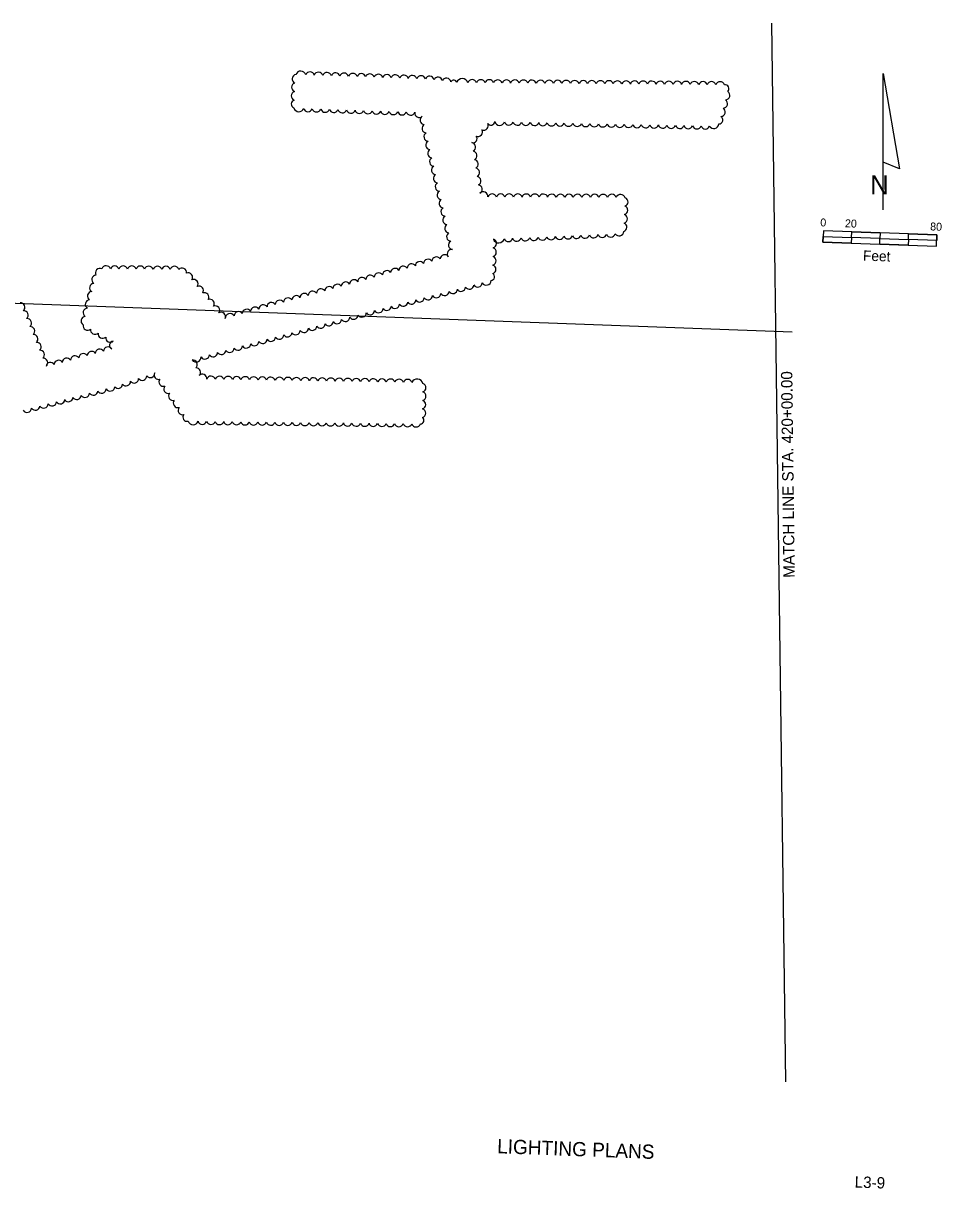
# Model space of a CAD drawing. Extents: x 919231 to 920524, y 636539 to 637379.
# Drawn here: x 919878 to 920524, y 636539 to 637359 of the extents above; entities that cross this region are included whole.
import ezdxf

# ---------------------------------------------------------------- set-up
doc = ezdxf.new("R2010")
doc.units = 0
for name, color, linetype in [('ActivePointCell_dp', 7, 'Continuous'), ('Cloud_dp', 7, 'Continuous'), ('MatchLines_dp', 7, 'Continuous'), ('NorthArw_dp', 7, 'Continuous'), ('Scale_dp', 7, 'Continuous'), ('TextMisc', 7, 'Continuous'), ('TextShtNo', 7, 'Continuous')]:
    doc.layers.add(name, color=color, linetype=linetype)

msp = doc.modelspace()

# ---------------------------------------------------------------- linework, layer by layer
at = {"layer": 'ActivePointCell_dp'}
msp.add_line((919374.23, 637180.22), (920419.17, 637141.7), dxfattribs=at)
at = {"layer": 'Cloud_dp'}
for centre, radius, start, end in [((920070.6, 637319.6), 3.18, 100.2465, 245.2465), ((920073.46, 637321.53), 3.63, 15.52249, 160.52249), ((920079.92, 637321.44), 3.15, 15.52249, 160.52249), ((920085.93, 637321.24), 3.15, 15.52249, 160.52249), ((920091.95, 637321.03), 3.15, 15.52249, 160.52249), ((920097.96, 637320.82), 3.15, 15.52249, 160.52249), ((920103.97, 637320.61), 3.15, 15.52249, 160.52249), ((920109.98, 637320.41), 3.15, 15.52249, 160.52249), ((920115.99, 637320.2), 3.15, 15.52249, 160.52249), ((920122, 637319.99), 3.15, 15.52249, 160.52249), ((920128.02, 637319.78), 3.15, 15.52249, 160.52249), ((920134.03, 637319.58), 3.15, 15.52249, 160.52249), ((920140.04, 637319.37), 3.15, 15.52249, 160.52249), ((920146.05, 637319.16), 3.15, 15.52249, 160.52249), ((920152.06, 637318.95), 3.15, 15.52249, 160.52249), ((920158.07, 637318.75), 3.15, 15.52249, 160.52249), ((920070.12, 637313.68), 3.15, 105.52249, 250.52249), ((920164.08, 637318.35), 3.22, 12.29046, 157.29046), ((920170.03, 637317.74), 3.09, 10.36222, 155.36222), ((920175.94, 637316.99), 3.15, 10.36222, 155.36222), ((920181.04, 637316.64), 2.19, 10.36222, 155.36222), ((920187.11, 637315.76), 4.12, 16.96357, 161.96357), ((920194.05, 637315.99), 3.15, 17.02441, 162.02441), ((920200.06, 637315.94), 3.15, 17.02441, 162.02441), ((920206.08, 637315.89), 3.15, 17.02441, 162.02441), ((920212.09, 637315.84), 3.15, 17.02441, 162.02441), ((920218.11, 637315.79), 3.15, 17.02441, 162.02441), ((920224.12, 637315.74), 3.15, 17.02441, 162.02441), ((920230.14, 637315.69), 3.15, 17.02441, 162.02441), ((920236.15, 637315.64), 3.15, 17.02441, 162.02441), ((920242.17, 637315.59), 3.15, 17.02441, 162.02441), ((920248.18, 637315.54), 3.15, 17.02441, 162.02441), ((920254.2, 637315.49), 3.15, 17.02441, 162.02441), ((920260.21, 637315.44), 3.15, 17.02441, 162.02441), ((920266.23, 637315.39), 3.15, 17.02441, 162.02441), ((920272.24, 637315.34), 3.15, 17.02441, 162.02441), ((920278.26, 637315.29), 3.15, 17.02441, 162.02441), ((920284.27, 637315.24), 3.15, 17.02441, 162.02441), ((920290.29, 637315.19), 3.15, 17.02441, 162.02441), ((920296.3, 637315.14), 3.15, 17.02441, 162.02441), ((920302.32, 637315.09), 3.15, 17.02441, 162.02441), ((920308.33, 637315.04), 3.15, 17.02441, 162.02441), ((920314.35, 637314.99), 3.15, 17.02441, 162.02441), ((920320.36, 637314.94), 3.15, 17.02441, 162.02441), ((920326.38, 637314.89), 3.15, 17.02441, 162.02441), ((920332.39, 637314.84), 3.15, 17.02441, 162.02441), ((920338.41, 637314.79), 3.15, 17.02441, 162.02441), ((920344.42, 637314.74), 3.15, 17.02441, 162.02441), ((920350.44, 637314.69), 3.15, 17.02441, 162.02441), ((920356.45, 637314.64), 3.15, 17.02441, 162.02441), ((920362.47, 637314.59), 3.15, 17.02441, 162.02441), ((920368.48, 637314.54), 3.15, 17.02441, 162.02441), ((920371.96, 637312.68), 2.81, 314.36029, 99.36029), ((920069.91, 637307.66), 3.15, 105.52249, 250.52249), ((920372.21, 637308.03), 3.15, 271.96447, 56.96447), ((920069.62, 637301.96), 2.84, 105.52249, 250.52249), ((920072.18, 637300.16), 3.62, 193.99327, 338.99327), ((920078.6, 637299.7), 3.15, 195.52249, 340.52249), ((920084.61, 637299.5), 3.15, 195.52249, 340.52249), ((920090.63, 637299.29), 3.15, 195.52249, 340.52249), ((920096.64, 637299.08), 3.15, 195.52249, 340.52249), ((920102.65, 637298.87), 3.15, 195.52249, 340.52249), ((920108.66, 637298.67), 3.15, 195.52249, 340.52249), ((920114.67, 637298.46), 3.15, 195.52249, 340.52249), ((920120.69, 637298.25), 3.15, 195.52249, 340.52249), ((920126.7, 637298.04), 3.15, 195.52249, 340.52249), ((920368.98, 637296.44), 3.15, 271.96447, 56.96447), ((920370.59, 637302.23), 3.15, 271.96447, 56.96447), ((920132.71, 637297.84), 3.15, 195.52249, 340.52249), ((920138.72, 637297.63), 3.15, 195.52249, 340.52249), ((920144.73, 637297.42), 3.15, 195.52249, 340.52249), ((920150.74, 637297.21), 3.15, 195.52249, 340.52249), ((920156.78, 637295.6), 3.12, 169.68331, 314.68331), ((920160.56, 637290.67), 3.15, 120.30502, 265.30502), ((920207.23, 637289.73), 2.65, 211.4846, 356.4846), ((920213.36, 637290.58), 3.62, 196.3247, 341.3247), ((920219.82, 637290.31), 3.15, 196.3247, 341.3247), ((920225.83, 637290.18), 3.15, 196.3247, 341.3247), ((920231.84, 637290.06), 3.15, 196.3247, 341.3247), ((920237.86, 637289.94), 3.15, 196.3247, 341.3247), ((920243.87, 637289.81), 3.15, 196.3247, 341.3247), ((920367.5, 637290.83), 2.92, 271.96447, 56.96447), ((920161.9, 637284.8), 3.15, 120.30502, 265.30502), ((920163.23, 637278.93), 3.15, 120.30502, 265.30502), ((920198.19, 637282.31), 3.15, 245.167, 30.167), ((920202.24, 637286.76), 3.15, 245.167, 30.167), ((920249.89, 637289.69), 3.15, 196.3247, 341.3247), ((920255.9, 637289.57), 3.15, 196.3247, 341.3247), ((920261.91, 637289.44), 3.15, 196.3247, 341.3247), ((920267.93, 637289.32), 3.15, 196.3247, 341.3247), ((920273.94, 637289.2), 3.15, 196.3247, 341.3247), ((920279.96, 637289.07), 3.15, 196.3247, 341.3247), ((920285.97, 637288.95), 3.15, 196.3247, 341.3247), ((920291.98, 637288.83), 3.15, 196.3247, 341.3247), ((920298, 637288.7), 3.15, 196.3247, 341.3247), ((920304.01, 637288.58), 3.15, 196.3247, 341.3247), ((920310.03, 637288.46), 3.15, 196.3247, 341.3247), ((920316.04, 637288.33), 3.15, 196.3247, 341.3247), ((920322.05, 637288.21), 3.15, 196.3247, 341.3247), ((920328.07, 637288.09), 3.15, 196.3247, 341.3247), ((920334.08, 637287.96), 3.15, 196.3247, 341.3247), ((920340.1, 637287.84), 3.15, 196.3247, 341.3247), ((920346.11, 637287.72), 3.15, 196.3247, 341.3247), ((920352.12, 637287.59), 3.15, 196.3247, 341.3247), ((920358.14, 637287.47), 3.15, 196.3247, 341.3247), ((920364.13, 637288.21), 3.48, 210.14773, 355.14773), ((920164.56, 637273.07), 3.15, 120.30502, 265.30502), ((920194.57, 637277.6), 2.94, 253.86781, 38.86781), ((920193.28, 637271.61), 3.2, 296.5074, 81.5074), ((920165.9, 637267.2), 3.15, 120.30502, 265.30502), ((920194.25, 637265.63), 3.15, 296.5074, 81.5074), ((920167.23, 637261.34), 3.15, 120.30502, 265.30502), ((920168.56, 637255.47), 3.15, 120.30502, 265.30502), ((920195.19, 637259.69), 3.15, 296.5074, 81.5074), ((920196.13, 637253.75), 3.15, 296.5074, 81.5074), ((920169.9, 637249.61), 3.15, 120.30502, 265.30502), ((920197.07, 637247.81), 3.15, 296.5074, 81.5074), ((920171.23, 637243.74), 3.15, 120.30502, 265.30502), ((920172.56, 637237.87), 3.15, 120.30502, 265.30502), ((920198.02, 637241.92), 3.1, 296.5074, 81.5074), ((920201.82, 637236.96), 3.26, 352.82963, 137.82963), ((920173.9, 637232.01), 3.15, 120.30502, 265.30502), ((920208.05, 637235.59), 3.15, 17.23742, 162.23742), ((920214.07, 637235.56), 3.15, 17.23742, 162.23742), ((920220.08, 637235.53), 3.15, 17.23742, 162.23742), ((920226.1, 637235.51), 3.15, 17.23742, 162.23742), ((920232.11, 637235.48), 3.15, 17.23742, 162.23742), ((920238.13, 637235.45), 3.15, 17.23742, 162.23742), ((920244.14, 637235.42), 3.15, 17.23742, 162.23742), ((920250.16, 637235.4), 3.15, 17.23742, 162.23742), ((920256.17, 637235.37), 3.15, 17.23742, 162.23742), ((920262.19, 637235.34), 3.15, 17.23742, 162.23742), ((920268.21, 637235.31), 3.15, 17.23742, 162.23742), ((920274.22, 637235.29), 3.15, 17.23742, 162.23742), ((920280.24, 637235.26), 3.15, 17.23742, 162.23742), ((920286.25, 637235.23), 3.15, 17.23742, 162.23742), ((920292.34, 637235.18), 3.23, 17.23742, 162.23742), ((920298.54, 637235.04), 3.31, 15.55321, 160.55321), ((920300.7, 637233.11), 2.99, 284.8909, 69.8909), ((920175.23, 637226.14), 3.15, 120.30502, 265.30502), ((920300.11, 637221.25), 3.15, 284.8909, 69.8909), ((920300.38, 637227.26), 3.15, 284.8909, 69.8909), ((920176.56, 637220.28), 3.15, 120.30502, 265.30502), ((920177.9, 637214.41), 3.15, 120.30502, 265.30502), ((920299.86, 637215.32), 3.07, 284.8909, 69.8909), ((920179.23, 637208.55), 3.15, 120.30502, 265.30502), ((920212.69, 637208.16), 3.92, 200.46999, 345.46999), ((920219.44, 637208.26), 3.15, 200.05253, 345.05253), ((920225.45, 637208.53), 3.15, 200.05253, 345.05253), ((920231.46, 637208.79), 3.15, 200.05253, 345.05253), ((920237.47, 637209.06), 3.15, 200.05253, 345.05253), ((920243.48, 637209.33), 3.15, 200.05253, 345.05253), ((920249.49, 637209.6), 3.15, 200.05253, 345.05253), ((920255.5, 637209.87), 3.15, 200.05253, 345.05253), ((920261.5, 637210.13), 3.15, 200.05253, 345.05253), ((920267.51, 637210.4), 3.15, 200.05253, 345.05253), ((920273.52, 637210.67), 3.15, 200.05253, 345.05253), ((920279.53, 637210.94), 3.15, 200.05253, 345.05253), ((920285.54, 637211.2), 3.15, 200.05253, 345.05253), ((920291.55, 637211.47), 3.15, 200.05253, 345.05253), ((920297.36, 637212.46), 3.3, 213.2018, 358.2018), ((920179.58, 637196.54), 3.08, 76.43366, 221.43366), ((920180.56, 637202.68), 3.15, 120.30502, 265.30502), ((920207.88, 637197.7), 3.15, 286.32602, 71.32602), ((920207.99, 637203.76), 3.2, 286.32602, 71.32602), ((920157.23, 637187.98), 3.15, 32.93413, 177.93413), ((920163.03, 637189.59), 3.15, 32.93413, 177.93413), ((920168.82, 637191.19), 3.15, 32.93413, 177.93413), ((920174.62, 637192.79), 3.15, 32.93413, 177.93413), ((920207.76, 637191.68), 3.15, 286.32602, 71.32602), ((919932.08, 637183.12), 3.13, 64.44976, 209.44976), ((919936.46, 637184.96), 3.18, 17.06483, 162.06483), ((919942.5, 637184.93), 3.15, 17.06483, 162.06483), ((919948.52, 637184.88), 3.15, 17.06483, 162.06483), ((919954.53, 637184.83), 3.15, 17.06483, 162.06483), ((919960.55, 637184.79), 3.15, 17.06483, 162.06483), ((919966.56, 637184.74), 3.15, 17.06483, 162.06483), ((919972.58, 637184.7), 3.15, 17.06483, 162.06483), ((919978.59, 637184.65), 3.15, 17.06483, 162.06483), ((919984.61, 637184.61), 3.15, 17.06483, 162.06483), ((919989.93, 637183.38), 3.15, 351.91856, 136.91856), ((919994.22, 637180.01), 3.15, 326.82601, 111.82601), ((920128.24, 637179.98), 3.15, 32.93413, 177.93413), ((920134.03, 637181.58), 3.15, 32.93413, 177.93413), ((920139.83, 637183.18), 3.15, 32.93413, 177.93413), ((920145.63, 637184.78), 3.15, 32.93413, 177.93413), ((920151.43, 637186.38), 3.15, 32.93413, 177.93413), ((920207.19, 637180.36), 2.64, 274.65372, 59.65372), ((920207.64, 637185.67), 3.15, 286.32602, 71.32602), ((919928.02, 637172.61), 3.15, 92.99962, 237.99962), ((919929.52, 637178.44), 3.15, 92.99962, 237.99962), ((919998.02, 637175.36), 3.15, 326.82601, 111.82601), ((920099.24, 637171.98), 3.15, 32.93413, 177.93413), ((920105.04, 637173.58), 3.15, 32.93413, 177.93413), ((920110.84, 637175.18), 3.15, 32.93413, 177.93413), ((920116.64, 637176.78), 3.15, 32.93413, 177.93413), ((920122.44, 637178.38), 3.15, 32.93413, 177.93413), ((920192.13, 637174.77), 3.15, 211.95466, 356.95466), ((920197.95, 637176.28), 3.15, 211.95466, 356.95466), ((920204, 637177.91), 3.41, 211.95466, 356.95466), ((919926.51, 637166.79), 3.15, 92.99962, 237.99962), ((920001.84, 637170.71), 3.15, 326.82601, 111.82601), ((920005.65, 637166.06), 3.15, 326.82601, 111.82601), ((920070.25, 637163.97), 3.15, 32.93413, 177.93413), ((920076.05, 637165.57), 3.15, 32.93413, 177.93413), ((920081.85, 637167.17), 3.15, 32.93413, 177.93413), ((920087.65, 637168.77), 3.15, 32.93413, 177.93413), ((920093.45, 637170.38), 3.15, 32.93413, 177.93413), ((920163.01, 637167.27), 3.15, 211.95466, 356.95466), ((920168.83, 637168.77), 3.15, 211.95466, 356.95466), ((920174.66, 637170.27), 3.15, 211.95466, 356.95466), ((920180.48, 637171.77), 3.15, 211.95466, 356.95466), ((920186.3, 637173.27), 3.15, 211.95466, 356.95466), ((919876.27, 637158.91), 3.15, 309.77549, 94.77549), ((919923.5, 637155.14), 3.15, 92.99962, 237.99962), ((919925.01, 637160.96), 3.15, 92.99962, 237.99962), ((920009.46, 637161.4), 3.15, 326.82601, 111.82601), ((920013.27, 637156.75), 3.15, 326.82601, 111.82601), ((920041.26, 637155.97), 3.15, 32.93413, 177.93413), ((920047.06, 637157.57), 3.15, 32.93413, 177.93413), ((920052.86, 637159.17), 3.15, 32.93413, 177.93413), ((920058.66, 637160.77), 3.15, 32.93413, 177.93413), ((920064.45, 637162.37), 3.15, 32.93413, 177.93413), ((920128.13, 637158.28), 3.24, 212.27257, 357.27257), ((920133.97, 637159.75), 3.07, 211.95466, 356.95466), ((920139.71, 637161.26), 3.15, 211.95466, 356.95466), ((920145.53, 637162.76), 3.15, 211.95466, 356.95466), ((920151.36, 637164.26), 3.15, 211.95466, 356.95466), ((920157.18, 637165.77), 3.15, 211.95466, 356.95466), ((919878.55, 637153.34), 3.15, 309.77549, 94.77549), ((919880.83, 637147.78), 3.15, 309.77549, 94.77549), ((919921.99, 637149.3), 3.17, 92.99962, 237.99962), ((920017.44, 637152.4), 3.03, 335.17554, 120.17554), ((920023.62, 637151.01), 3.44, 32.93413, 177.93413), ((920029.66, 637152.77), 3.15, 32.93413, 177.93413), ((920035.46, 637154.37), 3.15, 32.93413, 177.93413), ((920098.99, 637150.49), 3.15, 212.45525, 357.45525), ((920104.8, 637152.04), 3.15, 212.45525, 357.45525), ((920110.62, 637153.59), 3.15, 212.45525, 357.45525), ((920116.43, 637155.14), 3.15, 212.45525, 357.45525), ((920122.24, 637156.7), 3.15, 212.45525, 357.45525), ((919883.11, 637142.21), 3.15, 309.77549, 94.77549), ((919923.43, 637145.94), 3.18, 167.73243, 312.73243), ((919928.69, 637143.02), 3.16, 169.51959, 314.51959), ((920069.93, 637142.72), 3.15, 212.45525, 357.45525), ((920075.75, 637144.28), 3.15, 212.45525, 357.45525), ((920081.56, 637145.83), 3.15, 212.45525, 357.45525), ((920087.37, 637147.38), 3.15, 212.45525, 357.45525), ((920093.18, 637148.93), 3.15, 212.45525, 357.45525), ((919885.39, 637136.64), 3.15, 309.77549, 94.77549), ((919887.67, 637131.08), 3.15, 309.77549, 94.77549), ((919934, 637140.2), 3.15, 169.51959, 314.51959), ((919939.31, 637137.38), 3.15, 169.51959, 314.51959), ((919941.88, 637132.21), 2.94, 96.84056, 241.84056), ((920035.07, 637133.41), 3.15, 212.45525, 357.45525), ((920040.88, 637134.96), 3.15, 212.45525, 357.45525), ((920046.69, 637136.52), 3.15, 212.45525, 357.45525), ((920052.5, 637138.07), 3.15, 212.45525, 357.45525), ((920058.31, 637139.62), 3.15, 212.45525, 357.45525), ((920064.12, 637141.17), 3.15, 212.45525, 357.45525), ((919889.95, 637125.51), 3.15, 309.77549, 94.77549), ((919920.42, 637123.19), 3.15, 32.6956, 177.6956), ((919926.23, 637124.77), 3.15, 32.6956, 177.6956), ((919932.03, 637126.34), 3.15, 32.6956, 177.6956), ((919937.84, 637127.92), 3.15, 32.6956, 177.6956), ((920006.01, 637125.65), 3.15, 212.45525, 357.45525), ((920011.82, 637127.2), 3.15, 212.45525, 357.45525), ((920017.63, 637128.75), 3.15, 212.45525, 357.45525), ((920023.44, 637130.31), 3.15, 212.45525, 357.45525), ((920029.25, 637131.86), 3.15, 212.45525, 357.45525), ((919892.23, 637119.9), 3.19, 309.77549, 94.77549), ((919897.24, 637117.14), 2.99, 29.03882, 174.03882), ((919903.01, 637118.46), 3.15, 32.6956, 177.6956), ((919908.81, 637120.04), 3.15, 32.6956, 177.6956), ((919914.62, 637121.61), 3.15, 32.6956, 177.6956), ((919999.87, 637123.9), 3.48, 215.9297, 0.9297), ((919997.43, 637118.63), 3.25, 311.78511, 96.78511), ((919956.24, 637108.7), 3.15, 216.46738, 1.46738), ((919961.93, 637110.65), 3.15, 216.46738, 1.46738), ((919967.62, 637112.61), 3.16, 216.46738, 1.46738), ((919973.25, 637111.11), 2.94, 147.54419, 292.54419), ((919976.85, 637106.44), 3.15, 141.43676, 286.43676), ((919999.96, 637113.16), 3.07, 311.78511, 96.78511), ((920004.25, 637108.76), 3.08, 351.83577, 136.83577), ((920010.29, 637107.33), 3.15, 16.5633, 161.5633), ((920016.31, 637107.23), 3.15, 16.5633, 161.5633), ((920022.32, 637107.13), 3.15, 16.5633, 161.5633), ((920028.34, 637107.03), 3.15, 16.5633, 161.5633), ((920034.35, 637106.93), 3.15, 16.5633, 161.5633), ((920040.37, 637106.83), 3.15, 16.5633, 161.5633), ((920046.38, 637106.74), 3.15, 16.5633, 161.5633), ((920052.4, 637106.64), 3.15, 16.5633, 161.5633), ((920058.41, 637106.54), 3.15, 16.5633, 161.5633), ((920064.42, 637106.44), 3.15, 16.5633, 161.5633), ((920070.44, 637106.34), 3.15, 16.5633, 161.5633), ((920076.45, 637106.24), 3.15, 16.5633, 161.5633), ((920082.47, 637106.15), 3.15, 16.5633, 161.5633), ((920088.48, 637106.05), 3.15, 16.5633, 161.5633), ((920094.5, 637105.95), 3.15, 16.5633, 161.5633), ((920100.51, 637105.85), 3.15, 16.5633, 161.5633), ((920106.53, 637105.75), 3.15, 16.5633, 161.5633), ((920112.54, 637105.65), 3.15, 16.5633, 161.5633), ((920118.55, 637105.56), 3.15, 16.5633, 161.5633), ((920124.57, 637105.46), 3.15, 16.5633, 161.5633), ((920130.58, 637105.36), 3.15, 16.5633, 161.5633), ((920136.6, 637105.26), 3.15, 16.5633, 161.5633), ((920155.41, 637104.38), 4.08, 12.15238, 157.15238), ((919933.33, 637101.63), 3.15, 211.96915, 356.96915), ((919939.31, 637103.23), 3.33, 211.96915, 356.96915), ((919945.04, 637104.81), 2.98, 216.14687, 1.14687), ((919950.55, 637106.74), 3.15, 216.46738, 1.46738), ((919980.2, 637101.45), 3.15, 141.43676, 286.43676), ((920142.61, 637105.16), 3.15, 16.5633, 161.5633), ((920148.63, 637105.06), 3.15, 16.5633, 161.5633), ((920158.45, 637102.34), 3.05, 286.8281, 71.8281), ((919898.39, 637092.61), 3.15, 211.96915, 356.96915), ((919904.21, 637094.11), 3.15, 211.96915, 356.96915), ((919910.04, 637095.62), 3.15, 211.96915, 356.96915), ((919915.86, 637097.12), 3.15, 211.96915, 356.96915), ((919921.68, 637098.62), 3.15, 211.96915, 356.96915), ((919927.51, 637100.13), 3.15, 211.96915, 356.96915), ((919983.56, 637096.46), 3.15, 141.43676, 286.43676), ((919986.92, 637091.47), 3.15, 141.43676, 286.43676), ((920158.28, 637090.41), 3.15, 286.8281, 71.8281), ((920158.35, 637096.42), 3.15, 286.8281, 71.8281), ((919880.91, 637088.1), 3.15, 211.96915, 356.96915), ((919886.74, 637089.61), 3.15, 211.96915, 356.96915), ((919892.56, 637091.11), 3.15, 211.96915, 356.96915), ((919990.28, 637086.48), 3.15, 141.43676, 286.43676), ((920158.21, 637084.39), 3.15, 286.8281, 71.8281), ((919993.45, 637081.63), 2.92, 141.43676, 286.43676), ((919997.74, 637079.86), 3.61, 196.51139, 341.51139), ((920004.18, 637079.63), 3.15, 196.8281, 341.8281), ((920010.2, 637079.56), 3.15, 196.8281, 341.8281), ((920016.21, 637079.49), 3.15, 196.8281, 341.8281), ((920022.23, 637079.42), 3.15, 196.8281, 341.8281), ((920028.24, 637079.35), 3.15, 196.8281, 341.8281), ((920034.26, 637079.28), 3.15, 196.8281, 341.8281), ((920040.27, 637079.21), 3.15, 196.8281, 341.8281), ((920046.29, 637079.14), 3.15, 196.8281, 341.8281), ((920052.3, 637079.06), 3.15, 196.8281, 341.8281), ((920058.32, 637078.99), 3.15, 196.8281, 341.8281), ((920064.33, 637078.92), 3.15, 196.8281, 341.8281), ((920070.35, 637078.85), 3.15, 196.8281, 341.8281), ((920076.36, 637078.78), 3.15, 196.8281, 341.8281), ((920082.38, 637078.71), 3.15, 196.8281, 341.8281), ((920088.39, 637078.64), 3.15, 196.8281, 341.8281), ((920094.41, 637078.57), 3.15, 196.8281, 341.8281), ((920100.42, 637078.5), 3.15, 196.8281, 341.8281), ((920106.44, 637078.43), 3.15, 196.8281, 341.8281), ((920112.45, 637078.36), 3.15, 196.8281, 341.8281), ((920118.47, 637078.29), 3.15, 196.8281, 341.8281), ((920124.48, 637078.22), 3.15, 196.8281, 341.8281), ((920130.5, 637078.15), 3.15, 196.8281, 341.8281), ((920136.51, 637078.08), 3.15, 196.8281, 341.8281), ((920142.53, 637078.01), 3.15, 196.8281, 341.8281), ((920148.54, 637077.94), 3.15, 196.8281, 341.8281), ((920154.57, 637077.87), 3.17, 196.8281, 341.8281), ((920157.65, 637079.37), 2.49, 268.67068, 53.67068)]:
    msp.add_arc(centre, radius, start, end, dxfattribs=at)
at = {"layer": 'MatchLines_dp'}
msp.add_line((920404.58, 637358.77), (920414.55, 636613.94), dxfattribs=at)
at = {"layer": 'NorthArw_dp'}
msp.add_line((920483.24, 637227.45), (920483.24, 637323.45), dxfattribs=at)
msp.add_lwpolyline([(920483.24, 637261.05), (920483.24, 637323.45), (920494.76, 637256.25)], close=True, dxfattribs=at)
at = {"layer": 'Scale_dp'}
for p, q in [((920441.12, 637212.82), (920440.83, 637204.82)), ((920521.07, 637209.87), (920441.12, 637212.82)), ((920520.77, 637201.88), (920521.07, 637209.87)), ((920440.83, 637204.82), (920520.77, 637201.88))]:
    msp.add_line(p, q, dxfattribs=at)
for points in [[(920440.83, 637204.82), (920440.98, 637208.82), (920460.96, 637208.08), (920460.81, 637204.09)], [(920460.96, 637208.08), (920461.11, 637212.08), (920481.1, 637211.34), (920480.95, 637207.35)], [(920480.8, 637203.35), (920480.95, 637207.35), (920500.93, 637206.61), (920500.79, 637202.61)], [(920500.93, 637206.61), (920501.08, 637210.61), (920521.07, 637209.87), (920520.92, 637205.87)]]:
    msp.add_lwpolyline(points, close=True, dxfattribs=at)

# ---------------------------------------------------------------- texts
at = {"layer": 'MatchLines_dp'}
msp.add_text(' MATCH LINE STA. 420+00.00', height=8, rotation=90.70251, dxfattribs=at).set_placement((920421.1, 636965.65))
at = {"layer": 'NorthArw_dp'}
msp.add_text('N', height=13.43, dxfattribs=at).set_placement((920474.12, 637238.32))
at = {"layer": 'Scale_dp'}
for s, height, p in [('0', 5.6, (920438.91, 637215.9)), ('20', 5.6, (920456.26, 637215.26)), ('80', 5.6, (920516.2, 637213.05)), ('Feet', 7.2, (920468.91, 637191.78))]:
    msp.add_text(s, height=height, rotation=357.88886, dxfattribs=at).set_placement(p)
at = {"layer": 'TextMisc'}
msp.add_text('        LIGHTING PLANS         ', height=10, rotation=357.88886, dxfattribs=at).set_placement((920181.79, 636564.7))
at = {"layer": 'TextShtNo'}
msp.add_text(' L3-9 ', height=8, rotation=357.88886, dxfattribs=at).set_placement((920460.08, 636539.57))

doc.saveas('drawing.dxf')
